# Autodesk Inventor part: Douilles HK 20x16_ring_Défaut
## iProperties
Shininess: 64.0
Length Units: 11269
Angle Units: 11279
Time Units: 11290
Mass Units: 11283
Length Display Precision: 3
Angle Display Precision: 2
Compacted: True
Part Number: Douilles HK 20x16_ring_Défaut
Document SubType Name: Modeling
Created: 2006-01
Material: Par défaut
Designer: riri
Density: 0.0
Volumn: 0.0
Area: 0.0
PropertySet Name: Model Information
Control State: 0
Master: False
Checked Out: False
Author: riri
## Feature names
1. Base1
